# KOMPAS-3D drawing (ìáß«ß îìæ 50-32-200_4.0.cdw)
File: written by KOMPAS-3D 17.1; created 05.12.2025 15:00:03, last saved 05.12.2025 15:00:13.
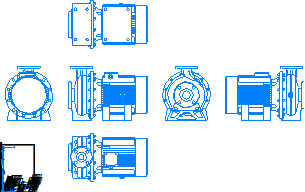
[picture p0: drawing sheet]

Sheet 1: A4, portrait

Title block, sheet 1: name: МНС 50-32-200_4.0; material: Сталь 10  ГОСТ 1050-88; mass: 146,85; sheets: 1; sheet format: A4

Views: Вид 1, Спереди, Проекционный вид 2, Проекционный вид 4, Проекционный вид 5, Проекционный вид 6
Referenced files in \\adlc.lan\data\АДЛ_ПКД\3D-модели\ADL production\Насосы ГРАНПАМП\Насосы ГРАНПАМП серии МНС\KOMPAS 3D\: Насос МНС 50-32-200_4.0.m3d
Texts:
  Andrey
  АДЛ
Dimensions and other numbers on the sheet: 1:1; 1; 146,85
